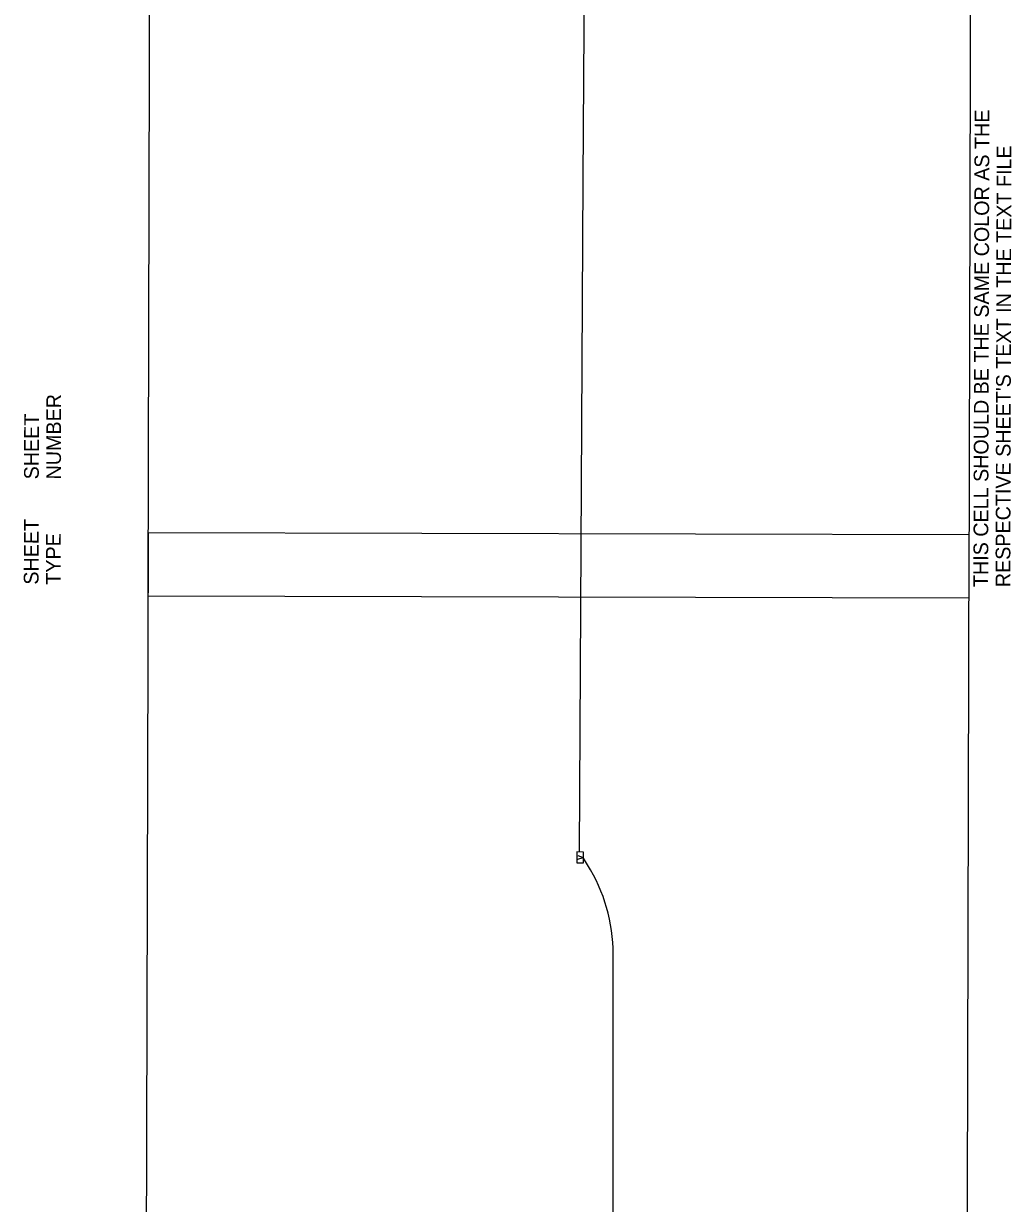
# Model space of a CAD drawing. Extents: x 601462 to 605493, y 331960 to 402715.
# Drawn here: x 602635 to 603808, y 371926 to 373327 of the extents above; entities that cross this region are included whole.
import ezdxf

# ---------------------------------------------------------------- set-up
doc = ezdxf.new("R2010")
doc.units = 0
for name, color, linetype in [('P_FTMS', 7, 'Continuous'), ('P_FTMSConduit', 7, 'Continuous'), ('P_MISC_TXT_1A (Construction)', 7, 'Continuous'), ('P_MISC_TXT_1B (Construction)', 7, 'Continuous')]:
    doc.layers.add(name, color=color, linetype=linetype)

# ---------------------------------------------------------------- blocks, each defined once
blk = doc.blocks.new('FTMS_FCV')
at = {"layer": 'P_FTMS'}
blk.add_line((12.7, 16.3), (0.6, -21.9), dxfattribs=at)
blk.add_lwpolyline([(39.1, 24.4), (-39.1, 24.4), (-39.1, -24.4), (39.1, -24.4)], close=True, dxfattribs=at)
blk.add_lwpolyline([(-12.1, 16.2), (0.6, -21.9)], dxfattribs=at)

msp = doc.modelspace()

# ---------------------------------------------------------------- linework, layer by layer
at = {"layer": 'P_FTMSConduit'}
for p, q in [((603304.3, 372327.8), (603299.5, 372335.5)), ((603334.6, 371466), (603334.7, 372221.7))]:
    msp.add_line(p, q, dxfattribs=at)
for points in [[(603299.2, 373140.9), (603302.7, 373679)], [(603294.7, 372342.9), (603299.2, 373140.9)]]:
    msp.add_lwpolyline(points, dxfattribs=at)
msp.add_arc((603134.7, 372221.7), 200, 359.9892, 32.041, dxfattribs=at)
at = {"layer": 'P_MISC_TXT_1A (Construction)'}
msp.add_lwpolyline([(603757.3, 372644.6), (603761.3, 374219.6), (602786.3, 374222.1), (602782.3, 372647.1)], close=True, dxfattribs=at)
msp.add_lwpolyline([(603757.3, 372644.6), (603761.3, 374219.6), (602786.3, 374222.1), (602782.3, 372647.1)], close=True, dxfattribs=at)
at = {"layer": 'P_MISC_TXT_1B (Construction)'}
msp.add_lwpolyline([(603753.4, 371144.6), (603757.5, 372719.6), (602782.5, 372722.1), (602778.4, 371147.1)], close=True, dxfattribs=at)
msp.add_lwpolyline([(603753.4, 371144.6), (603757.5, 372719.6), (602782.5, 372722.1), (602778.4, 371147.1)], close=True, dxfattribs=at)
msp.add_lwpolyline([(603753.4, 371144.6), (603757.5, 372719.6), (602782.5, 372722.1), (602778.4, 371147.1)], close=True, dxfattribs=at)
msp.add_lwpolyline([(603753.4, 371144.6), (603757.5, 372719.6), (602782.5, 372722.1), (602778.4, 371147.1)], close=True, dxfattribs=at)

# ---------------------------------------------------------------- block references
at = {"layer": 'P_FTMS', "xscale": 0.16404166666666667, "yscale": 0.16404166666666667, "rotation": 88.76248754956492}
msp.add_blockref('FTMS_FCV', (603295.5, 372336.5), dxfattribs=at)

# ---------------------------------------------------------------- texts
at = {"layer": 'P_MISC_TXT_1A (Construction)'}
for s, p in [('THIS CELL SHOULD BE THE SAME COLOR AS THE', (603779.9, 372657.5)), ('THIS CELL SHOULD BE THE SAME COLOR AS THE', (603779.9, 372657.5)), ("RESPECTIVE SHEET'S TEXT IN THE TEXT FILE", (603806.2, 372657.4)), ("RESPECTIVE SHEET'S TEXT IN THE TEXT FILE", (603806.2, 372657.4)), ('NUMBER', (602679, 372785.3)), ('NUMBER', (602679, 372785.3)), ('SHEET', (602652.7, 372785.4)), ('SHEET', (602652.7, 372785.4)), ('SHEET', (602652.4, 372660.4)), ('SHEET', (602652.4, 372660.4)), ('TYPE', (602678.7, 372660.3)), ('TYPE', (602678.7, 372660.3))]:
    msp.add_text(s, height=17.5, rotation=89.8526, dxfattribs=at).set_placement(p)

doc.saveas('drawing.dxf')
